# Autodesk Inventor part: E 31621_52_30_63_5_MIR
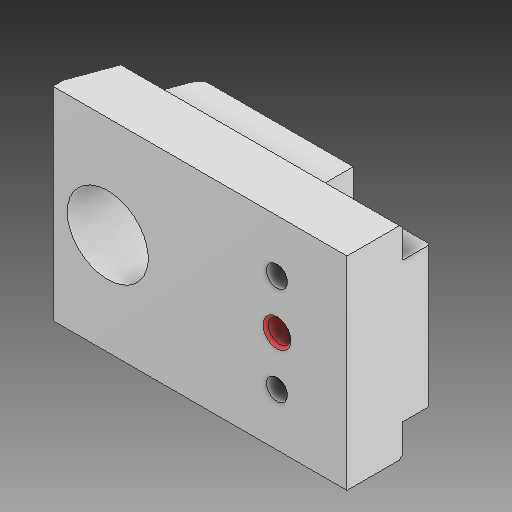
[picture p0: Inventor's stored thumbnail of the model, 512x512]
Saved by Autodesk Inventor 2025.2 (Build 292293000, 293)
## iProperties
Created: 2025-03
Part Number: E 31621_52_30_63_5_MIR
Material: Všeobecné
Document SubType Name: Modeling
Designer: Patrik
Mass: 11.8053 g
Surface Area: 48.6504 cm^2
Volume: 11.8053 cm^3
Density: 1 g/cm^3
Appearance: Výchozí
Author: Patrik
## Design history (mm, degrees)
derived "E 31621_52_30_63_5.ipt"
feature "Těleso1::E 31621_52_30_63_5.ipt" dims "d0" = 10
tag "Prvek štítků1"
node "Těleso1"
